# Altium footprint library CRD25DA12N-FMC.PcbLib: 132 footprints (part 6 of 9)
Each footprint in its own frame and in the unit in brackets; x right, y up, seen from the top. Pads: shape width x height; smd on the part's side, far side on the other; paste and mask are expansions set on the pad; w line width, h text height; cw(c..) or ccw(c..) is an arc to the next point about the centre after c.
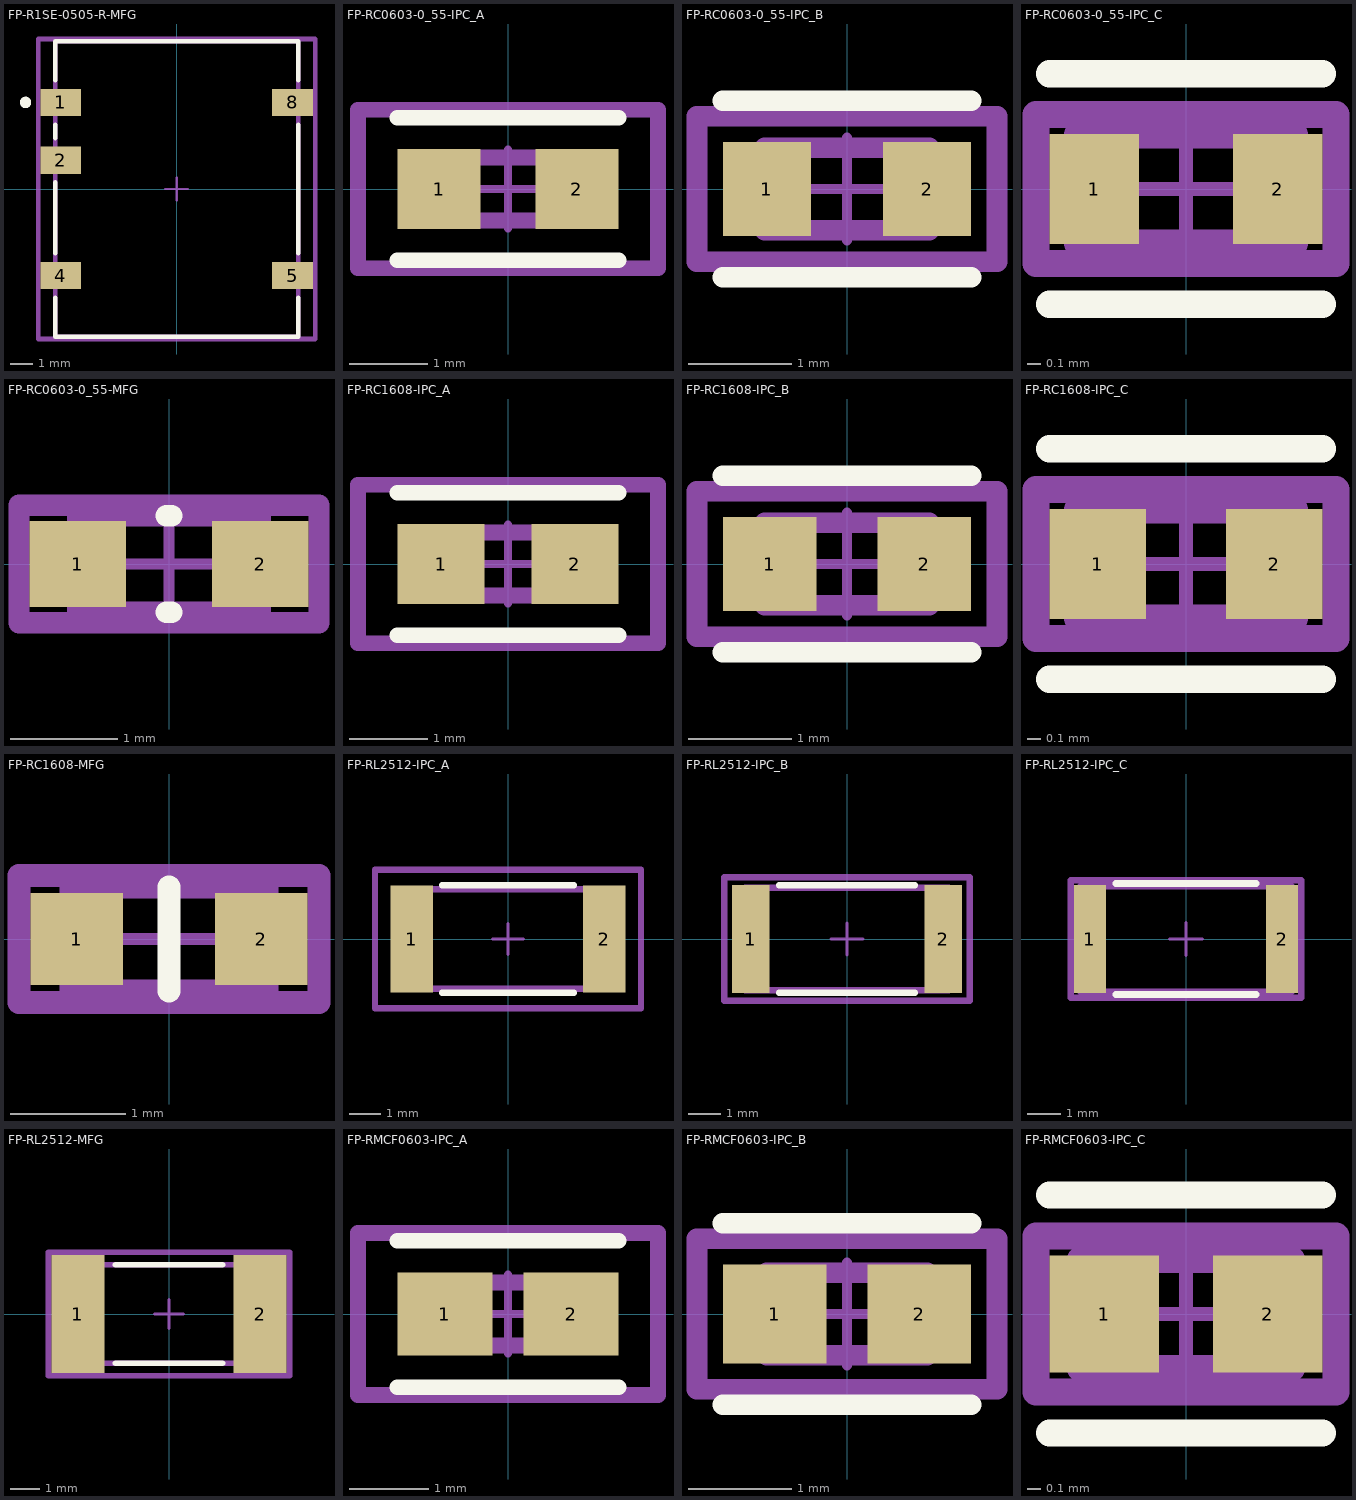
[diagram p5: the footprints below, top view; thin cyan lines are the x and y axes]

## FP-R1SE-0505-R-MFG [mm]
pads (5):
  rect 1.8x1.2 smd paste+0 mask+0: 1(-5.1,3.81) 2(-5.1,1.27) 4(-5.1,-3.81) 5(5.1,-3.81) 8(5.1,3.81)
Top Overlay:
  circle w0.25: c-6.65,3.81 r0.125
  lines w0.2: -5.35,-4.785 -5.35,-6.5 5.35,-6.5 5.35,-4.785 ; -5.35,-2.835 -5.35,0.295 ; -5.35,2.245 -5.35,2.835 ; -5.35,4.785 -5.35,6.5 5.35,6.5 5.35,4.785 ; 5.35,-2.835 5.35,2.835
Mechanical 5:
  lines w0.2: -6.1,-6.6 -6.1,6.6 6.1,6.6 6.1,-6.6 -6.1,-6.6
  text ".Designator" at 0,0.188 h1
Mechanical 13:
  lines w0.2: -5.35,-6.5 -5.35,6.5 5.35,6.5 5.35,-6.5 -5.35,-6.5
Mechanical 15:
  lines w0.2: -6.1,-6.6 -6.1,6.6 6.1,6.6 6.1,-6.6 -6.1,-6.6
Mechanical 16:
  lines w0.1: -0.5,0 0.5,0 ; 0,-0.5 0,0.5
3D body "IC_Recom_Power_R1SE-0505-R_eec.STEP": height 0.25, standoff 0, extent -6.1,-6.6 6.1,6.6

## FP-RC0603-0_55-IPC_A [mm]
pads (2):
  rect 1.059x1.012 smd paste+0 mask+0: 1(-0.877,0) 2(0.877,0)
Top Overlay:
  lines w0.2: -1.406,-0.906 1.406,-0.906 ; -1.406,0.906 1.406,0.906
Mechanical 5:
  lines w0.2: -1.906,-1.006 1.906,-1.006 1.906,1.006 -1.906,1.006 -1.906,-1.006
  text ".Designator" at 0,0.188 h1
Mechanical 13:
  lines w0.2: -0.8,-0.4 0.8,-0.4 0.8,0.4 -0.8,0.4 -0.8,-0.4
Mechanical 15:
  lines w0.2: -1.906,-1.006 1.906,-1.006 1.906,1.006 -1.906,1.006 -1.906,-1.006
Mechanical 16:
  lines w0.1: -0.5,0 0.5,0 ; 0,-0.5 0,0.5
3D body "Res_Yageo_RC0603FR-07100KL_eec.STEP": height 0.25, standoff 0, extent -1.906,-1.006 1.906,1.006

## FP-RC0603-0_55-IPC_B [mm]
pads (2):
  rect 0.859x0.912 smd paste+0 mask+0: 1(-0.777,0) 2(0.777,0)
Top Overlay:
  lines w0.2: -1.206,-0.856 1.206,-0.856 ; -1.206,0.856 1.206,0.856
Mechanical 5:
  lines w0.2: -1.456,-0.706 1.456,-0.706 1.456,0.706 -1.456,0.706 -1.456,-0.706
  text ".Designator" at 0,0.188 h1
Mechanical 13:
  lines w0.2: -0.8,-0.4 0.8,-0.4 0.8,0.4 -0.8,0.4 -0.8,-0.4
Mechanical 15:
  lines w0.2: -1.456,-0.706 1.456,-0.706 1.456,0.706 -1.456,0.706 -1.456,-0.706
Mechanical 16:
  lines w0.1: -0.5,0 0.5,0 ; 0,-0.5 0,0.5
3D body "Res_Yageo_RC0603FR-07100KL_eec.STEP": height 0.25, standoff 0, extent -1.456,-0.706 1.456,0.706

## FP-RC0603-0_55-IPC_C [mm]
pads (2):
  rect 0.659x0.812 smd paste+0 mask+0: 1(-0.677,0) 2(0.677,0)
Top Overlay:
  lines w0.2: -1.006,-0.85 1.006,-0.85 ; -1.006,0.85 1.006,0.85
Mechanical 5:
  lines w0.2: -1.106,-0.55 -1.106,0.55 1.106,0.55 1.106,-0.55 -1.106,-0.55
  text ".Designator" at 0,0.188 h1
Mechanical 13:
  lines w0.2: -0.8,-0.4 -0.8,0.4 0.8,0.4 0.8,-0.4 -0.8,-0.4
Mechanical 15:
  lines w0.2: -1.106,-0.55 -1.106,0.55 1.106,0.55 1.106,-0.55 -1.106,-0.55
Mechanical 16:
  lines w0.1: -0.5,0 0.5,0 ; 0,-0.5 0,0.5
3D body "Res_Yageo_RC0603FR-07100KL_eec.STEP": height 0.25, standoff 0, extent -1.106,-0.55 1.106,0.55

## FP-RC0603-0_55-MFG [mm]
pads (2):
  rect 0.9x0.8 smd paste+0 mask+0: 1(-0.85,0) 2(0.85,0)
Top Overlay:
  lines w0.2: -0.025,-0.45 0.025,-0.45 ; -0.025,0.45 0.025,0.45
Mechanical 5:
  lines w0.2: -1.4,-0.55 1.4,-0.55 1.4,0.55 -1.4,0.55 -1.4,-0.55
  text ".Designator" at 0,0.188 h1
Mechanical 13:
  lines w0.2: -0.85,-0.45 0.85,-0.45 0.85,0.45 -0.85,0.45 -0.85,-0.45
Mechanical 15:
  lines w0.2: -1.4,-0.55 1.4,-0.55 1.4,0.55 -1.4,0.55 -1.4,-0.55
Mechanical 16:
  lines w0.1: -0.5,0 0.5,0 ; 0,-0.5 0,0.5
3D body "Res_Yageo_RC0603FR-07100KL_eec.STEP": height 0.25, standoff 0, extent -1.4,-0.55 1.4,0.55

## FP-RC1608-IPC_A [mm]
pads (2):
  rect 1.11x1.012 smd paste+0 mask+0: 1(-0.851,0) 2(0.851,0)
Top Overlay:
  lines w0.2: -1.406,-0.906 1.406,-0.906 ; -1.406,0.906 1.406,0.906
Mechanical 5:
  lines w0.2: -1.906,-1.006 1.906,-1.006 1.906,1.006 -1.906,1.006 -1.906,-1.006
  text ".Designator" at 0,0.188 h1
Mechanical 13:
  lines w0.2: -0.8,-0.4 0.8,-0.4 0.8,0.4 -0.8,0.4 -0.8,-0.4
Mechanical 15:
  lines w0.2: -1.906,-1.006 1.906,-1.006 1.906,1.006 -1.906,1.006 -1.906,-1.006
Mechanical 16:
  lines w0.1: -0.5,0 0.5,0 ; 0,-0.5 0,0.5
3D body "Res_Samsung_RC1608F7873CS_eec.STEP": height 0.25, standoff 0, extent -1.906,-1.006 1.906,1.006

## FP-RC1608-IPC_B [mm]
pads (2):
  rect 0.91x0.912 smd paste+0 mask+0: 1(-0.751,0) 2(0.751,0)
Top Overlay:
  lines w0.2: -1.206,-0.856 1.206,-0.856 ; -1.206,0.856 1.206,0.856
Mechanical 5:
  lines w0.2: -1.456,-0.706 1.456,-0.706 1.456,0.706 -1.456,0.706 -1.456,-0.706
  text ".Designator" at 0,0.188 h1
Mechanical 13:
  lines w0.2: -0.8,-0.4 0.8,-0.4 0.8,0.4 -0.8,0.4 -0.8,-0.4
Mechanical 15:
  lines w0.2: -1.456,-0.706 1.456,-0.706 1.456,0.706 -1.456,0.706 -1.456,-0.706
Mechanical 16:
  lines w0.1: -0.5,0 0.5,0 ; 0,-0.5 0,0.5
3D body "Res_Samsung_RC1608F7873CS_eec.STEP": height 0.25, standoff 0, extent -1.456,-0.706 1.456,0.706

## FP-RC1608-IPC_C [mm]
pads (2):
  rect 0.71x0.812 smd paste+0 mask+0: 1(-0.651,0) 2(0.651,0)
Top Overlay:
  lines w0.2: -1.006,-0.85 1.006,-0.85 ; -1.006,0.85 1.006,0.85
Mechanical 5:
  lines w0.2: -1.106,-0.55 1.106,-0.55 1.106,0.55 -1.106,0.55 -1.106,-0.55
  text ".Designator" at 0,0.188 h1
Mechanical 13:
  lines w0.2: -0.8,-0.4 0.8,-0.4 0.8,0.4 -0.8,0.4 -0.8,-0.4
Mechanical 15:
  lines w0.2: -1.106,-0.55 1.106,-0.55 1.106,0.55 -1.106,0.55 -1.106,-0.55
Mechanical 16:
  lines w0.1: -0.5,0 0.5,0 ; 0,-0.5 0,0.5
3D body "Res_Samsung_RC1608F7873CS_eec.STEP": height 0.25, standoff 0, extent -1.106,-0.55 1.106,0.55

## FP-RC1608-MFG [mm]
pads (2):
  rect 0.8x0.8 smd paste+0 mask+0: 1(-0.8,0) 2(0.8,0)
Top Overlay:
  lines w0.2: 0,-0.45 0,0.45
Mechanical 5:
  lines w0.2: -1.3,-0.55 1.3,-0.55 1.3,0.55 -1.3,0.55 -1.3,-0.55
  text ".Designator" at 0,0 h1
Mechanical 13:
  lines w0.2: -0.85,-0.45 0.85,-0.45 0.85,0.45 -0.85,0.45 -0.85,-0.45
Mechanical 15:
  lines w0.2: -1.3,-0.55 1.3,-0.55 1.3,0.55 -1.3,0.55 -1.3,-0.55
Mechanical 16:
  lines w0.1: -0.5,0 0.5,0 ; 0,-0.5 0,0.5
3D body "Res_Samsung_RC1608F7873CS_eec.STEP": height 0.25, standoff 0, extent -1.3,-0.55 1.3,0.55

## FP-RL2512-IPC_A [mm]
pads (2):
  rect 1.358x3.458 smd paste+0 mask+0: 1(-3.102,0) 2(3.102,0)
Top Overlay:
  lines w0.2: -2.123,-1.729 2.123,-1.729 ; -2.123,1.729 2.123,1.729
Mechanical 5:
  lines w0.2: -4.281,-2.229 -4.281,2.229 4.281,2.229 4.281,-2.229 -4.281,-2.229
  text ".Designator" at 0,0.188 h1
Mechanical 13:
  lines w0.2: -3.175,-1.6 -3.175,1.6 3.175,1.6 3.175,-1.6 -3.175,-1.6
Mechanical 15:
  lines w0.2: -4.281,-2.229 -4.281,2.229 4.281,2.229 4.281,-2.229 -4.281,-2.229
Mechanical 16:
  lines w0.1: -0.5,0 0.5,0 ; 0,-0.5 0,0.5
3D body "Res_YAGEO_RL2512FK-070R1L_eec.STEP": height 0.25, standoff 0, extent -4.281,-2.229 4.281,2.229

## FP-RL2512-IPC_B [mm]
pads (2):
  rect 1.158x3.358 smd paste+0 mask+0: 1(-3.002,0) 2(3.002,0)
Top Overlay:
  lines w0.2: -2.123,-1.679 2.123,-1.679 ; -2.123,1.679 2.123,1.679
Mechanical 5:
  lines w0.2: -3.831,-1.929 -3.831,1.929 3.831,1.929 3.831,-1.929 -3.831,-1.929
  text ".Designator" at 0,0.188 h1
Mechanical 13:
  lines w0.2: -3.175,-1.6 -3.175,1.6 3.175,1.6 3.175,-1.6 -3.175,-1.6
Mechanical 15:
  lines w0.2: -3.831,-1.929 -3.831,1.929 3.831,1.929 3.831,-1.929 -3.831,-1.929
Mechanical 16:
  lines w0.1: -0.5,0 0.5,0 ; 0,-0.5 0,0.5
3D body "Res_YAGEO_RL2512FK-070R1L_eec.STEP": height 0.25, standoff 0, extent -3.831,-1.929 3.831,1.929

## FP-RL2512-IPC_C [mm]
pads (2):
  rect 0.958x3.258 smd paste+0 mask+0: 1(-2.902,0) 2(2.902,0)
Top Overlay:
  lines w0.2: -2.123,-1.675 2.123,-1.675 ; -2.123,1.675 2.123,1.675
Mechanical 5:
  lines w0.2: -3.481,-1.775 3.481,-1.775 3.481,1.775 -3.481,1.775 -3.481,-1.775
  text ".Designator" at 0,0.188 h1
Mechanical 13:
  lines w0.2: -3.175,-1.6 3.175,-1.6 3.175,1.6 -3.175,1.6 -3.175,-1.6
Mechanical 15:
  lines w0.2: -3.481,-1.775 3.481,-1.775 3.481,1.775 -3.481,1.775 -3.481,-1.775
Mechanical 16:
  lines w0.1: -0.5,0 0.5,0 ; 0,-0.5 0,0.5
3D body "Res_YAGEO_RL2512FK-070R1L_eec.STEP": height 0.25, standoff 0, extent -3.481,-1.775 3.481,1.775

## FP-RL2512-MFG [mm]
pads (2):
  rect 1.8x4 smd paste+0 mask+0: 1(-3.1,0) 2(3.1,0)
Top Overlay:
  lines w0.2: -1.825,-1.675 1.825,-1.675 ; -1.825,1.675 1.825,1.675
Mechanical 5:
  lines w0.2: -4.1,-2.1 4.1,-2.1 4.1,2.1 -4.1,2.1 -4.1,-2.1
  text ".Designator" at 0,0.188 h1
Mechanical 13:
  lines w0.2: -3.225,-1.675 3.225,-1.675 3.225,1.675 -3.225,1.675 -3.225,-1.675
Mechanical 15:
  lines w0.2: -4.1,-2.1 4.1,-2.1 4.1,2.1 -4.1,2.1 -4.1,-2.1
Mechanical 16:
  lines w0.1: -0.5,0 0.5,0 ; 0,-0.5 0,0.5
3D body "Res_YAGEO_RL2512FK-070R1L_eec.STEP": height 0.25, standoff 0, extent -4.1,-2.1 4.1,2.1

## FP-RMCF0603-IPC_A [mm]
pads (2):
  rect 1.206x1.058 smd paste+0 mask+0: 1(-0.801,0) 2(0.801,0)
Top Overlay:
  lines w0.2: -1.404,-0.929 1.404,-0.929 ; -1.404,0.929 1.404,0.929
Mechanical 5:
  lines w0.2: -1.904,-1.029 1.904,-1.029 1.904,1.029 -1.904,1.029 -1.904,-1.029
  text ".Designator" at 0,0.188 h1
Mechanical 13:
  lines w0.2: -0.775,-0.4 0.775,-0.4 0.775,0.4 -0.775,0.4 -0.775,-0.4
Mechanical 15:
  lines w0.2: -1.904,-1.029 1.904,-1.029 1.904,1.029 -1.904,1.029 -1.904,-1.029
Mechanical 16:
  lines w0.1: -0.5,0 0.5,0 ; 0,-0.5 0,0.5
3D body "Res_Stackpole_Electronics_RMCF0603JT1M80_eec.STEP": height 0.25, standoff 0, extent -1.904,-1.029 1.904,1.029

## FP-RMCF0603-IPC_B [mm]
pads (2):
  rect 1.006x0.958 smd paste+0 mask+0: 1(-0.701,0) 2(0.701,0)
Top Overlay:
  lines w0.2: -1.204,-0.879 1.204,-0.879 ; -1.204,0.879 1.204,0.879
Mechanical 5:
  lines w0.2: -1.454,-0.729 1.454,-0.729 1.454,0.729 -1.454,0.729 -1.454,-0.729
  text ".Designator" at 0,0.188 h1
Mechanical 13:
  lines w0.2: -0.775,-0.4 0.775,-0.4 0.775,0.4 -0.775,0.4 -0.775,-0.4
Mechanical 15:
  lines w0.2: -1.454,-0.729 1.454,-0.729 1.454,0.729 -1.454,0.729 -1.454,-0.729
Mechanical 16:
  lines w0.1: -0.5,0 0.5,0 ; 0,-0.5 0,0.5
3D body "Res_Stackpole_Electronics_RMCF0603JT1M80_eec.STEP": height 0.25, standoff 0, extent -1.454,-0.729 1.454,0.729

## FP-RMCF0603-IPC_C [mm]
pads (2):
  rect 0.806x0.858 smd paste+0 mask+0: 1(-0.601,0) 2(0.601,0)
Top Overlay:
  lines w0.2: -1.004,-0.875 1.004,-0.875 ; -1.004,0.875 1.004,0.875
Mechanical 5:
  lines w0.2: -1.104,-0.575 1.104,-0.575 1.104,0.575 -1.104,0.575 -1.104,-0.575
  text ".Designator" at 0,0.188 h1
Mechanical 13:
  lines w0.2: -0.775,-0.4 0.775,-0.4 0.775,0.4 -0.775,0.4 -0.775,-0.4
Mechanical 15:
  lines w0.2: -1.104,-0.575 1.104,-0.575 1.104,0.575 -1.104,0.575 -1.104,-0.575
Mechanical 16:
  lines w0.1: -0.5,0 0.5,0 ; 0,-0.5 0,0.5
3D body "Res_Stackpole_Electronics_RMCF0603JT1M80_eec.STEP": height 0.25, standoff 0, extent -1.104,-0.575 1.104,0.575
